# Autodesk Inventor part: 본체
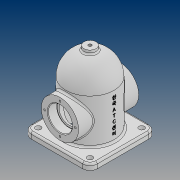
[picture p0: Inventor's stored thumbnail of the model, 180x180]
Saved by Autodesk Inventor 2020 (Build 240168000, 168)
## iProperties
Created: 2021-08
Part Number: 본체
Material: 일반
Document SubType Name: Modeling
Designer: PC312-
Density: 1 g/cm^3
Appearance: 기본값
Author: PC312-
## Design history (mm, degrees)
sketch "스케치1"
  geometry: L1 (0, 0)-(129, 0); L2 (84, 40)-(0, 40); L3 (0, 40)-(0, 32); L4 (0, 32)-(84, 32); L5 (129, 0)-(129, 10); L6 (129, 10)-(122.73, 10); A1 r 40 centre (84, 0) between (122.73, 10) and (84, 40); A2 r 32 centre (84, 0) between (116, 0) and (84, 32)
  constraints: 13 end point, 4 horizontal, 4 point on circle, 3 point on line, 2 centre point, 2 vertical, 2 vertical alignment, 1 coincident
  dimensions: "d1" = 80 diameter of A1; "d2" = 64 diameter of A2; "d10" = 129 distance of L1.start L1.end; "d11" = 20 diameter of L6 L1; "d12" = 84 distance of L1.start A1.centre
revolve "회전1" sketch "스케치1" stored, may be unused: angle "d3" = 90 deg
sketch "스케치2"
  geometry: L1 (55, -55)-(-55, -55); L2 (-55, -55)-(-55, 55); L3 (-55, 55)-(55, 55); L4 (55, 55)-(55, -55); C1 r 40 at (0, 0) reference; 1 further point
  constraints: 8 end point, 2 parallel, 1 horizontal, 1 perpendicular
  dimensions: "d4" = 110 distance of L1.start L1.end; "d5" = 110 distance of L1.end L2.end; "d6" = 55 distance from line of point (0, 0) L1; "d7" = 55 distance from line of point (0, 0) L4
extrude "돌출1" join sketch "스케치2" distance "d8" = 10; taper "d9" = 0 deg
node "작업 평면1"
sketch "스케치3"
  geometry: L1 (-55, 0)-(55, 0) reference; C1 r 31 at (0, 48); 2 further points
  constraints: 1 centre point, 1 midpoint, 1 vertical alignment
  dimensions: "d14" = 62 diameter of C1; "d15" = 48 distance from line of L1 C1.centre
extrude "돌출2" join sketch "스케치3" stored distance "d16" = 10; taper "d17" = 0 deg
sketch "스케치4"
  geometry: C1 r 20 at (0, 0); C2 r 31 at (0, 0) reference; 1 further point
  constraints: 1 centre point, 1 concentric
  dimensions: "d18" = 40 diameter of C1
extrude "돌출3" cut sketch "스케치4" distance "d19" = 15; taper "d20" = 0 deg
sketch "스케치5"
  geometry: L1 (-55, -48)-(55, -48) reference; C1 r 20 at (0, 0) reference; 3 further points
  constraints: 1 midpoint, 1 vertical alignment
  dimensions: "d21" = 25.5 distance of C1.centre point (0, 25.5)
hole "구멍1" sketch "스케치5" at (0, 25.5) diameter "d22" = 3.242; stored, may be unused: countersink angle "d26" = 90 deg, drill point angle "d28" = 118 deg; dims "d23" = 8, "d24" = 4, "d25" = 2, "d27" = 10
sketch "스케치6"
  geometry: C1 r 16.5 at (0, 0); C2 r 20 at (0, 0) reference; 1 further point
  constraints: 1 centre point, 1 concentric
  dimensions: "d32" = 33 diameter of C1
extrude "돌출4" cut sketch "스케치6" extent not by distance; stored distance "d33" = 15; taper "d34" = 0 deg
sketch "스케치7"
  geometry: C1 r 10 at (0, 0) reference; 2 further points
  constraints: 1 coincident
hole "구멍2" sketch "스케치7" at (0, 0) diameter "d35" = 5.1881; stored, may be unused: countersink angle "d39" = 90 deg, drill point angle "d41" = 118 deg; dims "d36" = 12, "d37" = 4, "d38" = 2, "d40" = 20
fillet "모깎기1" dims "d42" = 12
sketch "스케치8"
  geometry: C1 r 4.5 at (-43, 43); A1 r 12 centre (-43, 43) between (-43, 55) and (-55, 43) reference; 1 further point
  constraints: 1 centre point, 1 concentric
  dimensions: "d43" = 9 diameter of C1
extrude "돌출5" cut sketch "스케치8" extent not by distance; stored distance "d44" = 15; taper "d45" = 0 deg
fillet "모깎기2" dims "d52" = 0.3
fillet "모깎기3" dims "d53" = 3
chamfer "모따기1" distance "d54" = 1; stored, may be unused: second distance "d55" = 2, angle "d56" = 45 deg
node "작업 평면2"
sketch "스케치9"
  geometry: L1 (0, 43)-(0, -43) reference; 3 further points
  constraints: 1 horizontal alignment, 1 midpoint, 1 other
  dimensions: "d58" = 48 distance from line of L1 point (48, 0)
feature "엠보싱1" sketch "스케치9" dims "d1" = 80, "d2" = 64, "d10" = 129, "d11" = 20, "d12" = 84, "d59" = 0.5, "d60" = 0
node "솔리드1"
pattern_circular "원형 패턴1" dims angle "d30" = 360 deg
mirror "미러1"
pattern_linear "직사각형 패턴1" dims "d48" = 86, "d51" = 86
feature "A9D066F2-1C7D-4E18-AEED-F7BC21143FA4" dims "d22" = 3.242, "d23" = 8, "d24" = 4, "d25" = 2, "d26" = 90 deg, "d27" = 10, "d28" = 118 deg
other parameters: "d57" = 53.25
